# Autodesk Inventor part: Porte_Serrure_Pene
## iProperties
Created: 2009-01
Part Number: Porte_Serrure_Pene
Document SubType Name: Modeling
Designer: claivier
Author: claivier
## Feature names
1. Base1
